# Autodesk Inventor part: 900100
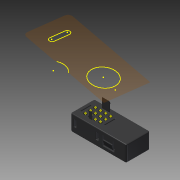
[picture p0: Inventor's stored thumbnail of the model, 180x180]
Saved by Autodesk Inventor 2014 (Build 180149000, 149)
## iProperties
Created: 2007-12
Part Number: 900100
Document SubType Name: Modeling
Designer: EP
Density: 1.425 g/cm^3
Mass: 54.0389 g
Surface Area: 125.096 cm^2
Volume: 37.922 cm^3
Material: Acetal Resin, Black
Description: 1200 POWER SEAT SWITCH CONTROL
Appearance: Dark Gray
Component Category: Electrical
Author: EP
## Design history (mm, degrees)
sketch "Sketch1"
  geometry: L1 (-35, 15)-(35, 15); L2 (35, 15)-(35, -15); L3 (35, -15)-(-35, -15); L4 (-35, -15)-(-35, 15); 1 further point
  constraints: 8 end point, 2 parallel, 1 horizontal, 1 perpendicular
  dimensions: "d0" = 70 distance of L1.start L1.end; "d1" = 35 distance from line of point (0, 0) L2 (= 0.5 x d0); "d2" = 30 distance of L3.end L1.start; "d3" = 15 distance from line of L1 point (0, 0) (= 0.5 x d2)
extrude "Extrusion1" new body sketch "Sketch1" distance "d4" = 20; taper "d5" = 0 deg
sketch "Sketch2"
  geometry: C1 r 1.905 at (-25, 6.35); 1 further point
  constraints: 1 centre point
  dimensions: "d6" = 3.81 diameter of C1; "d7" = 6.35 vertical distance of point (0, 0) C1.centre; "d8" = 25 horizontal distance of point (0, 0) C1.centre
extrude "Extrusion2" cut sketch "Sketch2" distance "d9" = 6.35; taper "d10" = 0 deg
chamfer "Chamfer1" distance "d11" = 0.254; stored, may be unused: second distance "d12" = 2, angle "d13" = 45 deg
sketch "Sketch3"
  geometry: C1 r 1.905 at (0, 0) reference; C2 r 0.711 at (0, 0); C3 r 0.635 at (0, 0)
  constraints: 2 centre point, 2 coincident
  dimensions: "d14" = 0.0762 radial gap between concentric circles of C2 C3; "d15" = 1.27 diameter of C3
extrude "Extrusion3" join sketch "Sketch3" distance "d16" = 3.81; taper "d17" = 0 deg
sketch "Sketch4"
  geometry: C1 r 1.905 at (0, 0) reference; C2 r 1.27 at (0, 0)
  constraints: 1 centre point, 1 coincident
  dimensions: "d18" = 2.54 diameter of C2
extrude "Extrusion4" join sketch "Sketch4" distance "d19" = 0.254; taper "d20" = 0 deg
fillet "Fillet1" dims "d21" = 0.127
pattern_linear "Rectangular Pattern1" dims "d24" = 6.35, "d27" = 6.35
workplane "Work Plane1"
sketch "Sketch5"
  geometry: L1 (-4.191, 20)-(-8.509, 20) reference; L2 (-4.191, 20)-(-8.509, 20) reference; L3 (2.159, 20)-(-2.159, 20) reference; L4 (2.159, 20)-(-2.159, 20) reference; L5 (8.509, 20)-(4.191, 20) reference; L6 (8.509, 20)-(4.191, 20) reference; L7 (15, 20)-(-15, 20) reference; L8 (-15, 20)-(15, 20) reference; L9 (8.509, 20)-(4.191, 20) reference; L10 (8.509, 20)-(4.191, 20) reference; L11 (2.159, 20)-(-2.159, 20) reference; L12 (2.159, 20)-(-2.159, 20) reference; L13 (-4.191, 20)-(-8.509, 20) reference; L14 (-4.191, 20)-(-8.509, 20) reference; L15 (9.525, 20)-(9.525, 32.89); L16 (9.525, 32.89)-(11.39, 28.89); L17 (11.39, 28.89)-(10.795, 28.89); L18 (10.795, 28.89)-(10.795, 20); L19 (10.795, 20)-(9.525, 20); 1 further point
  constraints: 10 end point, 3 perpendicular, 2 point on line, 1 parallel
  dimensions: "d29" = 9.525 distance from line of point (0, 0) L15; "d30" = 1.27 distance between parallel lines of L18 L15; "d31" = 8.89 distance between parallel lines of L8 L17; "d32" = 4 distance from line of L15.end L17; "d33" = 25 deg angle of L15 L16
extrude "Extrusion5" join sketch "Sketch5" stored distance "d34" = 8.89; taper "d35" = 0 deg
fillet "Fillet2" dims "d36" = 0.127
fillet "Fillet3" dims "d37" = 0.5
sketch "Sketch6"
  geometry: L1 (9.025, 20)-(10.795, 20) reference; L2 (10.795, 20)-(9.025, 20) reference; L3 (-4.191, 20)-(-8.509, 20) reference; L4 (-4.191, 20)-(-8.509, 20) reference; L5 (2.159, 20)-(-2.159, 20) reference; L6 (2.159, 20)-(-2.159, 20) reference; L7 (8.509, 20)-(4.191, 20) reference; L8 (8.509, 20)-(4.191, 20) reference; L9 (15, 20)-(-15, 20) reference; L10 (-15, 20)-(15, 20) reference; L11 (8.509, 20)-(4.191, 20) reference; L12 (8.509, 20)-(4.191, 20) reference; L13 (2.159, 20)-(-2.159, 20) reference; L14 (2.159, 20)-(-2.159, 20) reference; L15 (-4.191, 20)-(-8.509, 20) reference; L16 (-4.191, 20)-(-8.509, 20) reference; L17 (-8.89, 20)-(-8.89, 26.35); L18 (-8.89, 26.35)-(-8.539, 26.35); L19 (-8.539, 26.35)-(-9.449, 28.85); L20 (-9.449, 28.85)-(-9.449, 20); L21 (-9.449, 20)-(-8.89, 20); 1 further point
  constraints: 10 end point, 4 perpendicular, 2 point on line
  dimensions: "d42" = 0.5588 distance between parallel lines of L20 L17; "d43" = 8.89 distance from line of point (0, 0) L17; "d44" = 6.35 distance between parallel lines of L9 L18; "d45" = 2.5 distance from line of L19.end L18; "d46" = 20 deg angle of L20 L19
extrude "Extrusion6" join sketch "Sketch6" stored distance "d47" = 3.81; taper "d48" = 0 deg
fillet "Fillet4" dims "d49" = 0.05
fillet "Fillet5" dims "d50" = 0.5
sketch "Sketch7"
  geometry: L1 (-15.475, 21)-(-15.475, -21) reference; L2 (-30.842, 6.35)-(-30.08, 6.35); L3 (-30.08, 6.35)-(-30.08, -6.35); L4 (-30.08, -6.35)-(-30.842, -6.35); L5 (-30.842, -6.35)-(-30.842, 6.35); 1 further point
  constraints: 8 end point, 2 parallel, 1 horizontal, 1 perpendicular
  dimensions: "d51" = 6.35 distance from line of point (0, 0) L2 (= 0.5 x d52); "d52" = 12.7 distance of L4.end L2.start; "d53" = 0.762 distance of L3.end L4.end; "d54" = 14.605 distance between parallel lines of L1 L3
extrude "Extrusion7" cut sketch "Sketch7" distance "d55" = 10; taper "d56" = 0 deg
sketch "Sketch8"
  geometry: L1 (7.158, -6.92)-(4.158, -6.92); L2 (4.158, -6.92)-(4.158, -14.92); L3 (4.158, -14.92)-(7.158, -14.92); L4 (7.158, -14.92)-(7.158, -6.92); L5 (0, -20)-(70, -20) reference; L6 (19.525, 4)-(19.525, -24) reference; L7 (4.158, -20)-(4.158, -10) reference; L8 (4.158, -20)-(4.158, -10) reference
  constraints: 8 end point, 2 parallel, 1 collinear, 1 horizontal, 1 perpendicular
  dimensions: "d57" = 5.08 distance between parallel lines of L5 L3; "d58" = 8 distance of L3.end L1.start; "d59" = 3 distance of L1.start L1.end
extrude "Extrusion8" cut sketch "Sketch8" stored distance "d61" = 15; taper "d62" = 0 deg
fillet "Fillet6" dims "d63" = 0.5
fillet "Fillet7" dims "d64" = 0.5
fillet "Fillet8" dims "d65" = 0.5
mirror "Mirror1"
sketch "Sketch9"
  geometry: C1 r 5 at (-17.5, 0); C2 r 5 at (17.5, 0); 1 further point
  constraints: 2 centre point, 2 horizontal alignment, 1 equal radius
  dimensions: "d66" = 10 diameter of C1; "d67" = 35 distance of C2.centre C1.centre; "d68" = 17.5 distance of point (0, 0) C2.centre (= 0.5 x d67)
extrude "Extrusion9" cut sketch "Sketch9" distance "d69" = 5; taper "d70" = 0 deg
sketch "Sketch10"
  geometry: C1 r 5 at (0, 0) reference; C2 r 3.5 at (0, 0); C3 r 4.25 at (0, 0)
  constraints: 2 centre point, 2 coincident
  dimensions: "d71" = 0.75 radial gap between concentric circles of C3 C2; "d72" = 7 diameter of C2
extrude "Extrusion10" join sketch "Sketch10" distance "d73" = 3; taper "d74" = 0 deg
mirror "Mirror2"
sketch "Sketch11"
  geometry: C1 r 2.159 at (-25, -6.35) reference
node "1"
sketch "Sketch12"
  geometry: C1 r 2.159 at (-25, 0) reference
node "2"
sketch "Sketch13"
  geometry: C1 r 2.159 at (-25, 6.35) reference
node "3"
node "4"
sketch "Sketch14"
  geometry: C1 r 2.159 at (-18.65, 0) reference
node "5"
sketch "Sketch15"
  geometry: C1 r 2.159 at (-18.65, 6.35) reference
node "6"
sketch "Sketch16"
  geometry: C1 r 2.159 at (-12.3, -6.35) reference
node "7"
sketch "Sketch17"
  geometry: C1 r 2.159 at (-12.3, 0) reference
node "8"
sketch "Sketch18"
  geometry: C1 r 2.159 at (-12.3, 6.35) reference
node "9"
sketch "Sketch19"
  geometry: C1 r 2.159 at (-5.95, -6.35) reference
node "10"
sketch "Sketch20"
  geometry: C1 r 2.159 at (-5.95, 0) reference
node "11"
sketch "Sketch21"
  geometry: C1 r 2.159 at (-5.95, 6.35) reference
node "12"
fillet "Fillet9" dims "d75" = 2
fillet "Fillet10" dims "d76" = 1
fillet "Fillet11" dims "d77" = 1
sketch "Sketch22"
  geometry: L1 (33, 25.489)-(33, -19.933) reference; L2 (38, 15)-(53, 15); L3 (53, 15)-(53, 3); L4 (53, 3)-(38, 3); L5 (38, 3)-(38, 15); L6 (31.63, -1)-(33.392, -1) reference; L7 (33.392, -1)-(31.63, -1) reference; L8 (24.891, -1)-(29.209, -1) reference; L9 (12.191, -1)-(16.509, -1) reference; L10 (24.891, -1)-(29.209, -1) reference; L11 (12.191, -1)-(16.509, -1) reference; L12 (24.891, -1)-(29.209, -1) reference; L13 (12.191, -1)-(16.509, -1) reference; L14 (5.841, -1)-(10.159, -1) reference; L15 (18.541, -1)-(22.859, -1) reference; L16 (5.841, -1)-(10.159, -1) reference; L17 (18.541, -1)-(22.859, -1) reference; L18 (5.841, -1)-(10.159, -1) reference; L19 (18.541, -1)-(22.859, -1) reference; L20 (13.08, -1)-(21.97, -1) reference; L21 (13.08, -1)-(21.97, -1) reference; L22 (19.43, -1)-(15.62, -1) reference; L23 (19.43, -1)-(15.62, -1) reference; L24 (1.658, -1)-(3.42, -1) reference; L25 (3.42, -1)-(1.658, -1) reference; L26 (66, -1)-(0, -1) reference; L27 (67, -1)-(66, -1) reference; L28 (66, -1)-(67, -1) reference; L29 (0, -1)-(66, -1) reference; L30 (-1, -1)-(0, -1) reference; L31 (0, -1)-(-1, -1) reference
  constraints: 8 end point, 2 parallel, 1 horizontal, 1 perpendicular
  dimensions: "d78" = 5 distance between parallel lines of L1 L5; "d79" = 15 distance of L2.start L2.end; "d80" = 4 distance between parallel lines of L26 L4; "d81" = 12 distance of L2.end L3.end
extrude "Extrusion11" cut sketch "Sketch22" distance "d82" = 4; taper "d83" = 0 deg
workplane "Work Plane2"
sketch "Sketch23"
  geometry: L1 (16, -8.15)-(16, -21.85) reference; L2 (16, -21.85)-(16, -8.15) reference; L3 (16, -23.509)-(16, -19.191) reference; L4 (16, -23.509)-(16, -19.191) reference; L5 (16, -17.159)-(16, -12.841) reference; L6 (16, -17.159)-(16, -12.841) reference; L7 (16, -10.809)-(16, -6.491) reference; L8 (16, -10.809)-(16, -6.491) reference; L9 (16, -10.809)-(16, -6.491) reference; L10 (16, -10.809)-(16, -6.491) reference; L11 (16, -17.159)-(16, -12.841) reference; L12 (16, -17.159)-(16, -12.841) reference; L13 (16, -23.509)-(16, -19.191) reference; L14 (16, -23.509)-(16, -19.191) reference; L15 (16, -5.975)-(16, -4.205) reference; L16 (16, -4.205)-(16, -5.975) reference; L17 (16, -23.39)-(16, -24.449) reference; L18 (16, -24.449)-(16, -23.39) reference; L19 (16, -8.15)-(16, -21.85) reference; L20 (16, -21.85)-(16, -8.15) reference; L21 (16, -28)-(16, -29) reference; L22 (16, -2)-(16, -28) reference; L23 (16, -1)-(16, -2) reference; L24 (16, -2)-(16, -1) reference; L25 (16, -28)-(16, -2) reference; L26 (16, -29)-(16, -28) reference; L27 (0, 0)-(0, -4) reference; L28 (0, 0)-(0, -4) reference; L29 (12, 0)-(12, -4) reference; L30 (12, 0)-(12, -4) reference; L31 (12, 0)-(8, 0); L32 (8, 0)-(8, 1.5); L33 (8, 1.5)-(1.338, -0.721); L34 (1.465, -1.5)-(12, -1.5); A1 r 0.4 centre (1.465, -1.1) between (1.338, -0.721) and (1.465, -1.5); 1 further point
  constraints: 8 end point, 3 perpendicular, 3 point on line, 2 point on circle, 2 tangent, 1 centre point
  dimensions: "d84" = 8 distance between parallel lines of L25 L32; "d85" = 1.5 distance between parallel lines of L31 L34; "d86" = 1.5 distance from line of L31 L32.end; "d88" = 9 distance from line of L32 point (-1, -1.5); "d93" = 0.4 radius of A1
extrude "Extrusion12" join sketch "Sketch23" stored distance "d89" = 11; taper "d90" = 0 deg
fillet "Fillet13" dims "d92" = 0.5
mirror "Mirror3"
feature "Composite1"
sketch "Sketch24"
  geometry: L1 (98.674, -18.302)-(98.674, -36.302) reference; L2 (92.674, -36.302)-(92.674, -18.302) reference; C1 r 15 at (28.39, -30.958) reference; A1 r 3 centre (95.674, -36.302) between (92.674, -36.302) and (98.674, -36.302) reference; A2 r 3 centre (95.674, -18.302) between (98.674, -18.302) and (92.674, -18.302) reference; 4 further points; 1 other entity
  constraints: 1 other
body "Solid1"
node "Projected Loop1"
node "Projected Loop2"
node "Projected Loop3"
node "Projected Loop4"
node "Projected Loop5"
node "Projected Loop6"
node "Projected Loop7"
workplane "Work Plane3"
body "Srf1"
other parameters: "d28" = -15.475
